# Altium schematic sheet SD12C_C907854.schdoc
size 127 x 101 mm
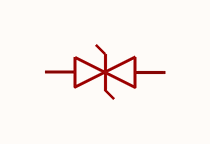
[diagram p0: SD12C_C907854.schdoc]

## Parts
D?  sd12c_c907854  [SOD-323_L1.7-W1.3-LS2.5-BI]  (value not drawn)

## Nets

Not connected (* = marked no-connect by the designer): D? 1 2

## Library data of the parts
D? = sd12c_c907854: 极性:双向;反向截止电压(Vrwm):12V;钳位电压:24V;峰值脉冲电流(Ipp):16A;峰值脉冲功率(Ppp):350W;击穿电压:13.3V;; Manufacturer: TECH PUBLIC(台舟); ManufacturerPart: SD12C; AddInBom: yes; ModelId: 3c4d3117213c44d8be2b8463c3660d20; ModelTransform: 98.425,51.181,0,0,0,0,-0.001,0.006,0; Polarity: 双向; Reverse Stand-Off Voltage (Vrwm): 12V; Clamping Voltage: 24V; Peak Pulse Current (Ipp): 16A; Peak Pulse Power Dissipation (Ppp): 350W; Voltage - Breakdown: 13.3V; Reverse Leakage Current (Ir): 500nA; Number of Channels: 单路; level of protection: IEC 61000-4-4；IEC 61000-4-2; Type: ESD; Junction Capacitance: 70pF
